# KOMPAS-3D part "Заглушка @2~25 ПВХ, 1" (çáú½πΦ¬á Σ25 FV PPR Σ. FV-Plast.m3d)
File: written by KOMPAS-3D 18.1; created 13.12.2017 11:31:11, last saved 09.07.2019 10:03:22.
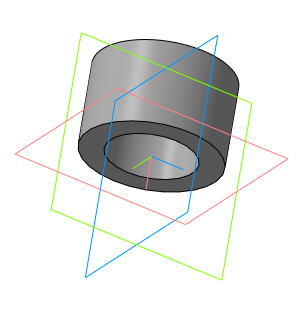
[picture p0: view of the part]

Document properties: Автор: Милов; Организация: Милов; Полное имя файла: D:\1 ПКИ 3D\Полипропиленовые фитинги, трубы\Заглушка ф25 FV PPR ф. FV-Plast.m3d

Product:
- Part/product: Заглушка @2~25 ПВХ  | designation 1
    Материал: Полипропилен  ГОСТ 26996-86 (density 900 kg/m3)
    Масса: 0.0161976
    Раздел спецификации: Прочие изделия
- Part/product: Заглушка @2~25 FV PPR ф. "FV-Plast"
    Материал: Полипропилен  ГОСТ 26996-86 (density 900 kg/m3)
    Масса: 0.0161976
    Раздел спецификации: Прочие изделия

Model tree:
1. Эскиз:1
2. Операция вращения:1  (labels: Полипропилен  ГОСТ 26996-86)
     Угол 1 = 360

Expressions: 37/2
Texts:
  Body Specification ( left align )
  Body Specificaton ( centered )

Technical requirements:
  Gost Type A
